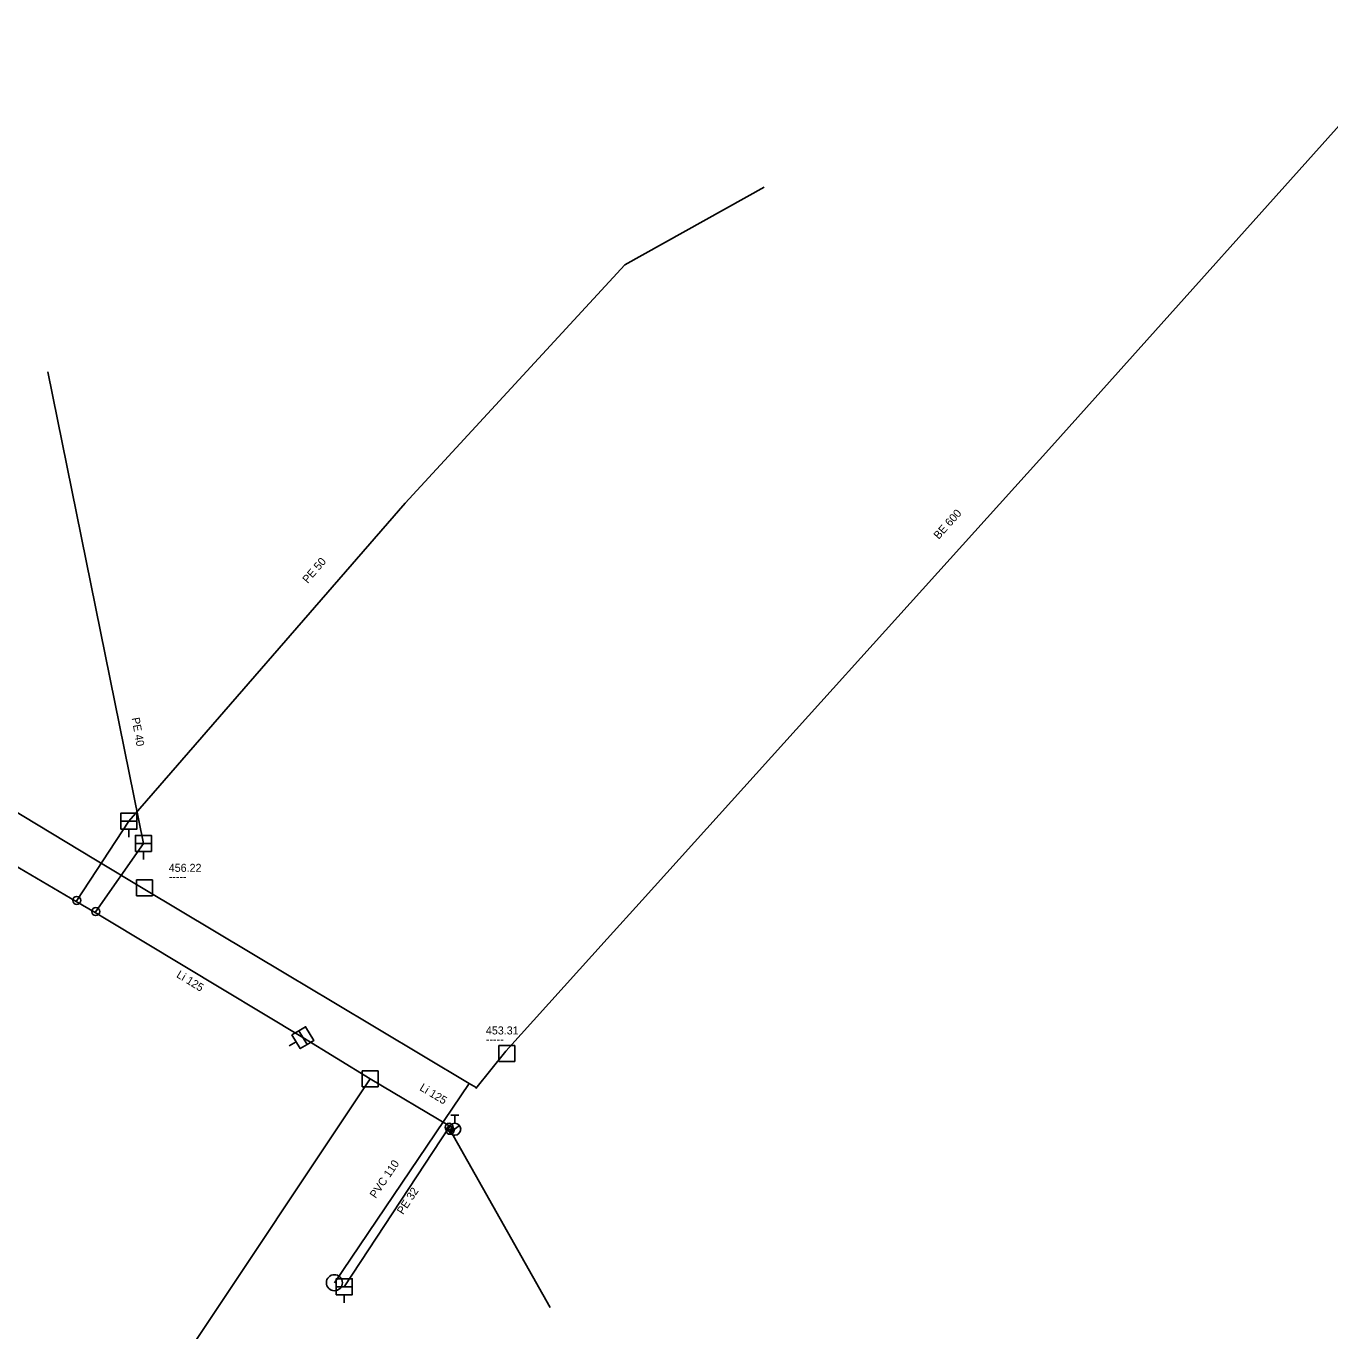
# Model space of a CAD drawing. Extents: x -755931 to -755358, y -1113840 to -1113401.
# Drawn here: x -755807.7 to -755644.8, y -1113709.1 to -1113546.1 of the extents above; entities that cross this region are included whole.
import ezdxf

# ---------------------------------------------------------------- set-up
doc = ezdxf.new("R2010")
doc.units = 0
doc.layers.add('Level 0', color=7, linetype='Continuous')

msp = doc.modelspace()

# ---------------------------------------------------------------- linework, layer by layer
at = {"layer": 'Level 0'}
for p, q in [((-755675.26, -1113593.69), (-755632.57, -1113546.05)), ((-755732.94, -1113575.87), (-755715.52, -1113566.17)), ((-755760.38, -1113605.65), (-755732.94, -1113575.87)), ((-755793.06, -1113648.18), (-755805.01, -1113589.27)), ((-755679.59, -1113598.53), (-755675.26, -1113593.69)), ((-755730.76, -1113655.29), (-755679.59, -1113598.53)), ((-755794.9, -1113645.4), (-755760.38, -1113605.65)), ((-755835.05, -1113628.54), (-755804.64, -1113646.86)), ((-755801.48, -1113655.43), (-755832.44, -1113637.23)), ((-755804.64, -1113646.86), (-755799.07, -1113650.22)), ((-755801.4, -1113655.3), (-755794.9, -1113645.4)), ((-755794.9, -1113647.4), (-755794.9, -1113646.4)), ((-755799.02, -1113656.7), (-755793.06, -1113648.18)), ((-755793.06, -1113650.18), (-755793.06, -1113649.18)), ((-755799.07, -1113650.22), (-755793.09, -1113653.82)), ((-755791.93, -1113652.72), (-755793.93, -1113652.72)), ((-755793.93, -1113652.72), (-755793.93, -1113654.72)), ((-755791.93, -1113654.72), (-755791.93, -1113652.72)), ((-755793.93, -1113654.72), (-755791.93, -1113654.72)), ((-755793.09, -1113653.82), (-755775.08, -1113664.59)), ((-755801.48, -1113655.43), (-755801.4, -1113655.3)), ((-755799.11, -1113656.82), (-755801.48, -1113655.43)), ((-755735.12, -1113660.11), (-755730.76, -1113655.29)), ((-755799.11, -1113656.82), (-755799.02, -1113656.7)), ((-755797.71, -1113657.64), (-755799.11, -1113656.82)), ((-755788.09, -1113663.44), (-755797.71, -1113657.64)), ((-755747.77, -1113674.15), (-755735.12, -1113660.11)), ((-755773.14, -1113672.45), (-755788.09, -1113663.44)), ((-755775.08, -1113664.59), (-755769.5, -1113667.92)), ((-755769.5, -1113667.92), (-755752.36, -1113678.17)), ((-755774.85, -1113673.48), (-755774, -1113672.97)), ((-755764.72, -1113677.61), (-755773.14, -1113672.45)), ((-755751.54, -1113678.79), (-755747.77, -1113674.15)), ((-755746.67, -1113673.44), (-755748.67, -1113673.44)), ((-755748.67, -1113673.44), (-755748.67, -1113675.44)), ((-755746.67, -1113675.44), (-755746.67, -1113673.44)), ((-755748.67, -1113675.44), (-755746.67, -1113675.44)), ((-755764.72, -1113677.61), (-755794.41, -1113722.14)), ((-755763.72, -1113676.61), (-755765.72, -1113676.61)), ((-755765.72, -1113676.61), (-755765.72, -1113678.61)), ((-755754.79, -1113683.52), (-755764.72, -1113677.61)), ((-755763.72, -1113678.61), (-755763.72, -1113676.61)), ((-755752.36, -1113678.17), (-755769.21, -1113703.07)), ((-755765.72, -1113678.61), (-755763.72, -1113678.61)), ((-755752.36, -1113678.17), (-755751.49, -1113678.69)), ((-755751.49, -1113678.69), (-755751.54, -1113678.79)), ((-755754.68, -1113682.14), (-755753.68, -1113682.14)), ((-755754.18, -1113683.14), (-755754.18, -1113682.14)), ((-755754.87, -1113683.65), (-755767.97, -1113703.58)), ((-755754.79, -1113683.52), (-755754.87, -1113683.65)), ((-755754.18, -1113683.89), (-755754.79, -1113683.52)), ((-755754.77, -1113684.35), (-755753.59, -1113683.43)), ((-755754.53, -1113683.68), (-755754.75, -1113684.03)), ((-755754.75, -1113684.03), (-755742.24, -1113706.15)), ((-755767.97, -1113705.58), (-755767.97, -1113704.58))]:
    msp.add_line(p, q, dxfattribs=at)
for points in [[(-755795.9, -1113645.4), (-755795.9, -1113644.4), (-755793.9, -1113644.4), (-755793.9, -1113645.4)], [(-755794.06, -1113648.18), (-755794.06, -1113647.18), (-755792.06, -1113647.18), (-755792.06, -1113648.18)], [(-755773.66, -1113671.59), (-755772.8, -1113671.08), (-755771.77, -1113672.79), (-755772.62, -1113673.31)], [(-755768.97, -1113703.58), (-755768.97, -1113702.58), (-755766.97, -1113702.58), (-755766.97, -1113703.58)]]:
    msp.add_lwpolyline(points, dxfattribs=at)
for points in [[(-755795.9, -1113646.4), (-755793.9, -1113646.4), (-755793.9, -1113645.4), (-755795.9, -1113645.4)], [(-755794.06, -1113649.18), (-755792.06, -1113649.18), (-755792.06, -1113648.18), (-755794.06, -1113648.18)], [(-755774.51, -1113672.11), (-755773.48, -1113673.82), (-755772.62, -1113673.31), (-755773.66, -1113671.59)], [(-755768.97, -1113704.58), (-755766.97, -1113704.58), (-755766.97, -1113703.58), (-755768.97, -1113703.58)]]:
    msp.add_lwpolyline(points, close=True, dxfattribs=at)
for centre, radius in [((-755801.4, -1113655.3), 0.5), ((-755799.02, -1113656.7), 0.5), ((-755754.87, -1113683.65), 0.5), ((-755754.75, -1113684.03), 0.5), ((-755754.18, -1113683.89), 0.75), ((-755769.21, -1113703.07), 1)]:
    msp.add_circle(centre, radius, dxfattribs=at)

# ---------------------------------------------------------------- texts
for s, rotation, p in [('BE 600', 48.137, (-755693.71, -1113610.25)), ('PE 50', 49.028, (-755772.55, -1113615.75)), ('PE 40', 279.995, (-755794.54, -1113632.52)), ('Li 125', 328.499, (-755789.03, -1113664.84)), ('Li 125', 328.92, (-755758.65, -1113678.96)), ('PVC 110', 55.914, (-755764.05, -1113692.6)), ('PE 32', 56.683, (-755760.64, -1113694.63))]:
    msp.add_text(s, height=1, rotation=rotation, dxfattribs=at).set_placement(p)
for s, p in [('456.22', (-755789.9, -1113651.73)), ('-----', (-755789.9, -1113652.83)), ('453.31', (-755750.28, -1113672.05)), ('-----', (-755750.28, -1113673.15))]:
    msp.add_text(s, height=1, dxfattribs=at).set_placement(p)

doc.saveas('drawing.dxf')
